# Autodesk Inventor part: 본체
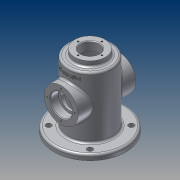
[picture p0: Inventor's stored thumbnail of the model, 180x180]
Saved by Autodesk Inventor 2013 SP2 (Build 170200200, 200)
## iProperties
Created: 2014-12
Part Number: 본체
Material: 알루미늄 6061
Document SubType Name: Modeling
Designer: CADB202
Density: 2.71 g/cm^3
Mass: 479.555 g
Surface Area: 607.373 cm^2
Volume: 176.957 cm^3
Author: CADB202
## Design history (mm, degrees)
sketch "스케치1"
  geometry: L1 (0, 51)-(0, -55); L2 (-14.5, 51)-(-22.5, 51); L3 (-22.5, 51)-(-22.5, 46); L4 (-25.5, 43)-(-29.5, 43); L5 (-32.5, 40)-(-32.5, -44); L6 (-35.5, -47)-(-49.5, -47); L7 (-52.5, -50)-(-52.5, -55); L8 (-52.5, -55)-(-27.5, -55); L9 (-13.5, 38)-(-24.5, 38); L10 (-27.5, 35)-(-27.5, -55); L11 (-13.5, 38)-(-13.5, 50); L12 (-14.5, 51)-(-13.5, 50); A1 r 3 centre (-24.5, 35) between (-24.5, 38) and (-27.5, 35); A2 r 3 centre (-25.5, 46) between (-25.5, 43) and (-22.5, 46); A3 r 3 centre (-29.5, 40) between (-29.5, 43) and (-32.5, 40); A4 r 3 centre (-35.5, -44) between (-35.5, -47) and (-32.5, -44); A5 r 3 centre (-49.5, -50) between (-49.5, -47) and (-52.5, -50); 4 further points
  constraints: 24 end point, 10 point on circle, 10 tangent, 6 parallel, 5 centre point, 4 point on line, 3 equal radius, 2 horizontal alignment, 2 perpendicular, 1 midpoint, 1 vertical, 1 vertical alignment
  dimensions: "d0" = 106 distance of L1.start L1.end; "d2" = 55 distance of point (0, 0) L1.end; "d3" = 105 diameter of L7 L1; "d4" = 65 diameter of L5 L1; "d5" = 45 diameter of L3 L1; "d6" = 8 distance of point (-52.5, -47) L7.end; "d7" = 98 distance between parallel lines of L4 L8; "d8" = 55 diameter of L10 L1; "d9" = 5 distance between parallel lines of L9 L4; "d10" = 27 diameter of L11 L1; "d11" = 3 radius of A1; "d12" = 1 distance of L2.start point (-13.5, 51); "d13" = 1 distance of L11.end point (-13.5, 51) (= d12); "d14" = 3 radius of A3
revolve "회전1" sketch "스케치1" stored, may be unused: angle "d15" = 90 deg
node "작업 평면1"
sketch "스케치2"
  geometry: C1 r 25 at (0, 0); 5 further points
  constraints: 1 centre point, 1 coincident, 1 vertical alignment, 5 other
  dimensions: "d17" = 50 diameter of C1; "d18" = 20.5 distance of point (0, 20.5) point (0, 0); "d23" = 360 deg dimension on C1.centre point (0, 20.5) (derived)
extrude "돌출1" join sketch "스케치2" stored distance "d19" = 10; taper "d20" = 0 deg
hole "구멍1" sketch "스케치2" diameter "d25" = 2.459; stored, may be unused: countersink angle "d29" = 90 deg, drill point angle "d31" = 118 deg; dims "d26" = 6, "d27" = 4, "d28" = 2, "d30" = 8
hole "구멍2" diameter "d34" = 25; stored, may be unused: countersink angle "d38" = 90 deg, drill point angle "d40" = 0 deg; dims "d32" = 10, "d33" = 10, "d35" = 6, "d36" = 32, "d37" = 12, "d39" = 8
sketch "스케치3"
  geometry: C1 r 22.5 at (0, 0) reference; 5 further points
  constraints: 1 horizontal alignment, 5 other
  dimensions: "d41" = 17.5 distance of point (17.5, 0) point (0, 0); "d44" = 360 deg dimension on C1.centre point (17.5, 0) (derived)
hole "구멍3" sketch "스케치3" at (17.5, 0), (0, 17.5), (-17.5, 0), (0, -17.5) diameter "d46" = 2.459; stored, may be unused: countersink angle "d50" = 90 deg, drill point angle "d52" = 118 deg; dims "d47" = 6, "d48" = 32, "d49" = 12, "d51" = 8
sketch "스케치4"
  geometry: L1 (0, 0)-(30.406, 30.406); L2 (0, 0)-(43, 0); C1 r 4 at (30.406, 30.406); C2 r 27.5 at (0, 0) reference; C3 r 4 at (-30.406, 30.406); C4 r 4 at (-30.406, -30.406); C5 r 4 at (30.406, -30.406)
  constraints: 4 centre point, 4 end point, 1 coincident, 1 equal length, 1 horizontal, 9 other
  dimensions: "d53" = 43 distance of L1.start L1.end; "d54" = 45 deg angle of L2 L1; "d55" = 8 diameter of C1; "d58" = 360 deg dimension on C2.centre C1.centre (derived)
extrude "돌출2" cut sketch "스케치4" stored distance "d60" = 10; taper "d61" = 0 deg
node "작업 평면2"
sketch "스케치5"
  geometry: L1 (29.5, 45)-(-29.5, 45) reference; 2 further points
  constraints: 1 vertical alignment, 1 other
  dimensions: "d62" = 9 distance from line of L1 point (0, 36)
feature "엠보싱1" sketch "스케치5" dims "d63" = 1, "d64" = 0
chamfer "모따기1" distance "d65" = 1; stored, may be unused: second distance "d66" = 2, angle "d67" = 45 deg
fillet "모깎기1" dims "d68" = 0.3, "d69" = 3
node "솔리드1"
mirror "대칭1"
other parameters: "d16" = 42.5
